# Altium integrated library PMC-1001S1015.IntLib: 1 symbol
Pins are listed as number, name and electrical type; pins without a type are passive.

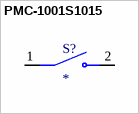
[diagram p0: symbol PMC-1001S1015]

## PMC-1001S1015
designator S?
MP: PMC-1001S1015
footprint SW_PMC-1001S1015
pins: 1 COM, 2 NO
